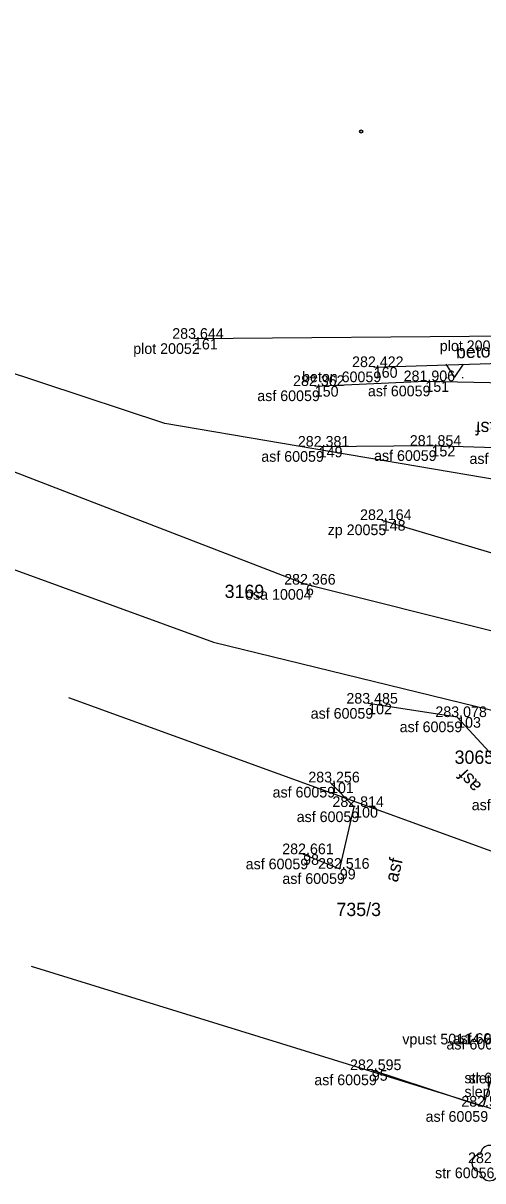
# Model space of a CAD drawing. Extents: x -728659 to -728362, y -1073110 to -1072943.
# Drawn here: x -728551.8 to -728525.9, y -1073069.6 to -1073004.3 of the extents above; entities that cross this region are included whole.
import ezdxf

# ---------------------------------------------------------------- set-up
doc = ezdxf.new("R2010")
doc.units = 0
for name, color, linetype in [('Vrstva 1', 7, 'Continuous'), ('Vrstva 17', 7, 'Continuous'), ('Vrstva 50', 7, 'Continuous'), ('Vrstva 51', 7, 'Continuous'), ('Vrstva 53', 7, 'Continuous'), ('Vrstva 55', 7, 'Continuous'), ('Vrstva 57', 7, 'Continuous'), ('Vrstva 58', 7, 'Continuous'), ('Vrstva 59', 7, 'Continuous'), ('Vrstva 60', 7, 'Continuous'), ('Vrstva 61', 7, 'Continuous'), ('Vrstva 62', 7, 'Continuous')]:
    doc.layers.add(name, color=color, linetype=linetype)

msp = doc.modelspace()

# ---------------------------------------------------------------- linework, layer by layer
at = {"layer": 'Vrstva 1'}
msp.add_lwpolyline([(-728462.112, -1073044.292), (-728486.957, -1073044.611), (-728498.776, -1073043.699), (-728511.695, -1073041.857), (-728514.393, -1073041.361), (-728535.912, -1073035.983), (-728560.369, -1073026.548)], dxfattribs=at)
at = {"layer": 'Vrstva 17'}
msp.add_line((-728522.835, -1073021.968), (-728542.221, -1073022.127), dxfattribs=at)
msp.add_lwpolyline([(-728531.636, -1073032.342), (-728514.713, -1073037.388), (-728514.509, -1073035.909)], dxfattribs=at)
at = {"layer": 'Vrstva 50'}
for centre, start, end in [((-728525.557, -1073068.089), 0, 180), ((-728526.057, -1073068.589), 90, 270), ((-728525.557, -1073069.089), 180, 0)]:
    msp.add_arc(centre, 0.5, start, end, dxfattribs=at)
at = {"layer": 'Vrstva 51'}
for points in [[(-728535.414, -1073024.787), (-728529.18, -1073024.517), (-728519.218, -1073024.728), (-728515.346, -1073023.472), (-728514.359, -1073023.043), (-728513.624, -1073022.497), (-728513.279, -1073022.092), (-728513.109, -1073021.591), (-728513.091, -1073020.945), (-728514.696, -1073012.189)], [(-728532.088, -1073023.721), (-728519.526, -1073023.322), (-728519.714, -1073021.793), (-728522.835, -1073021.968)], [(-728510.066, -1073037.464), (-728511.097, -1073030.537), (-728511.871, -1073029.55), (-728512.902, -1073029.227), (-728513.865, -1073029.238), (-728518.889, -1073028.771), (-728523.455, -1073028.329), (-728528.834, -1073028.159), (-728535.188, -1073028.207)], [(-728519.061, -1073052.066), (-728523.329, -1073047.846), (-728527.39, -1073043.448), (-728532.404, -1073042.69)], [(-728536.068, -1073051.177), (-728534.002, -1073051.999), (-728533.193, -1073048.516), (-728534.552, -1073047.131)], [(-728512.38, -1073063.734), (-728512.393, -1073063.245), (-728512.614, -1073062.698), (-728513.079, -1073062.079), (-728513.527, -1073061.773), (-728514.184, -1073061.553), (-728518.227, -1073061.285), (-728524.406, -1073061.017), (-728524.753, -1073061.334), (-728525.929, -1073065.41), (-728532.201, -1073063.347)]]:
    msp.add_lwpolyline(points, dxfattribs=at)
at = {"layer": 'Vrstva 53'}
msp.add_lwpolyline([(-728658.89, -1072943.19), (-728655.13, -1072951.34), (-728641.33, -1072971.93), (-728620.02, -1072997.18), (-728600.31, -1073011.5), (-728598.74, -1073012.6), (-728581.66, -1073022.5), (-728572.55, -1073027.78), (-728541.12, -1073039.22), (-728509.9, -1073046.86), (-728510.22, -1073036.28), (-728510.71, -1073032.54), (-728543.86, -1073026.9), (-728564.68, -1073020.02), (-728582.13, -1073004.22), (-728604.14, -1072988.92), (-728619.81, -1072972.56), (-728640.48, -1072947.72)], dxfattribs=at)
at = {"layer": 'Vrstva 55'}
for points in [[(-728549.3, -1073042.35), (-728519.8, -1073053.05), (-728515.13, -1073054.76), (-728512.7, -1073054.03), (-728510.66, -1073051.71), (-728509.9, -1073046.86)], [(-728551.4, -1073057.49), (-728537.29, -1073061.85), (-728523.51, -1073066.11), (-728519.8, -1073053.05)]]:
    msp.add_lwpolyline(points, dxfattribs=at)
at = {"layer": 'Vrstva 58'}
for p, q in [((-728528.005, -1073024.305), (-728527.955, -1073024.305)), ((-728527.105, -1073024.305), (-728527.055, -1073024.305))]:
    msp.add_line(p, q, dxfattribs=at)
msp.add_lwpolyline([(-728528.03, -1073023.555), (-728527.53, -1073024.305), (-728527.03, -1073023.555)], dxfattribs=at)
at = {"layer": 'Vrstva 59'}
msp.add_circle((-728532.798, -1073010.441), 0.0873, dxfattribs=at)
at = {"layer": 'Vrstva 60'}
for p, q in [((-728542.221, -1073022.127), (-728542.221, -1073022.127)), ((-728532.088, -1073023.721), (-728532.088, -1073023.721)), ((-728535.414, -1073024.787), (-728535.414, -1073024.787)), ((-728529.18, -1073024.517), (-728529.18, -1073024.517)), ((-728535.188, -1073028.207), (-728535.188, -1073028.207)), ((-728528.834, -1073028.159), (-728528.834, -1073028.159)), ((-728531.636, -1073032.342), (-728531.636, -1073032.342)), ((-728535.912, -1073035.983), (-728535.912, -1073035.983)), ((-728532.404, -1073042.69), (-728532.404, -1073042.69)), ((-728527.39, -1073043.448), (-728527.39, -1073043.448)), ((-728534.552, -1073047.131), (-728534.552, -1073047.131)), ((-728533.193, -1073048.516), (-728533.193, -1073048.516)), ((-728536.068, -1073051.177), (-728536.068, -1073051.177)), ((-728534.002, -1073051.999), (-728534.002, -1073051.999)), ((-728532.201, -1073063.347), (-728532.201, -1073063.347))]:
    msp.add_line(p, q, dxfattribs=at)

# ---------------------------------------------------------------- texts
at = {"layer": 'Vrstva 51'}
for s, rotation, p in [('beton chodnik', 1.81924, (-728527.449, -1073023.234)), ('asf', 178.1898, (-728525.002, -1073026.83)), ('asf', 132.71859, (-728525.981, -1073047.296)), ('asf', 76.92371, (-728530.752, -1073052.799))]:
    msp.add_text(s, height=0.75, rotation=rotation, dxfattribs=at).set_placement(p)
at = {"layer": 'Vrstva 57'}
for s, p in [('3169', (-728540.494, -1073036.734)), ('3065/18', (-728527.534, -1073046.083)), ('735/3', (-728534.192, -1073054.664))]:
    msp.add_text(s, height=0.75, dxfattribs=at).set_placement(p)
at = {"layer": 'Vrstva 60'}
for s, p in [('161', (-728542.221, -1073022.727)), ('160', (-728532.088, -1073024.321)), ('150', (-728535.414, -1073025.387)), ('151', (-728529.18, -1073025.117)), ('149', (-728535.188, -1073028.807)), ('152', (-728528.834, -1073028.759)), ('148', (-728531.636, -1073032.942)), ('6', (-728535.912, -1073036.583)), ('102', (-728532.404, -1073043.29)), ('103', (-728527.39, -1073044.048)), ('101', (-728534.552, -1073047.731)), ('100', (-728533.193, -1073049.116)), ('98', (-728536.068, -1073051.777)), ('99', (-728534.002, -1073052.599)), ('95', (-728532.201, -1073063.947))]:
    msp.add_text(s, height=0.6, dxfattribs=at).set_placement(p)
at = {"layer": 'Vrstva 61'}
for s, p in [('283.644', (-728543.446, -1073022.127)), ('282.422', (-728533.312, -1073023.721)), ('282.362', (-728536.638, -1073024.787)), ('281.906', (-728530.406, -1073024.517)), ('282.381', (-728536.367, -1073028.207)), ('281.854', (-728530.059, -1073028.159)), ('282.164', (-728532.861, -1073032.342)), ('282.366', (-728537.138, -1073035.983)), ('283.485', (-728533.632, -1073042.69)), ('283.078', (-728528.617, -1073043.448)), ('283.256', (-728535.778, -1073047.131)), ('282.814', (-728534.418, -1073048.516)), ('282.661', (-728537.247, -1073051.177)), ('282.516', (-728535.228, -1073051.999)), ('282.595', (-728533.429, -1073063.347)), ('282.536', (-728527.155, -1073065.41)), ('282.580', (-728526.776, -1073068.59))]:
    msp.add_text(s, height=0.6, dxfattribs=at).set_placement(p)
at = {"layer": 'Vrstva 62'}
for s, p in [('plot 20052 60059', (-728528.367, -1073022.818)), ('plot 20052', (-728545.645, -1073022.977)), ('beton 60059', (-728536.13, -1073024.571)), ('asf 60059', (-728532.419, -1073025.367)), ('asf 60059', (-728538.653, -1073025.637)), ('asf 60059', (-728538.427, -1073029.057)), ('asf 60059', (-728532.073, -1073029.009)), ('asf 60059', (-728526.694, -1073029.179)), ('zp 20055', (-728534.686, -1073033.192)), ('osa 10004', (-728539.339, -1073036.833)), ('asf 60059', (-728535.643, -1073043.54)), ('asf 60059', (-728530.629, -1073044.298)), ('asf 60059', (-728537.791, -1073047.981)), ('asf 60059', (-728526.568, -1073048.696)), ('asf 60059', (-728536.432, -1073049.366)), ('asf 60059', (-728539.307, -1073052.027)), ('asf 60059', (-728537.241, -1073052.849)), ('vpust 50114 60059 50177', (-728530.478, -1073061.899)), ('asf 60059', (-728527.645, -1073061.867)), ('asf 60059', (-728527.992, -1073062.184)), ('asf 60059', (-728535.44, -1073064.197)), ('str 60056', (-728526.981, -1073064.09)), ('slepci 60059', (-728526.746, -1073064.096)), ('slepci 60059', (-728526.978, -1073064.857)), ('asf 60059', (-728529.168, -1073066.26)), ('str 60056', (-728528.635, -1073069.44))]:
    msp.add_text(s, height=0.6, dxfattribs=at).set_placement(p)

doc.saveas('drawing.dxf')
